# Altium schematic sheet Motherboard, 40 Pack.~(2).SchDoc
size Legal
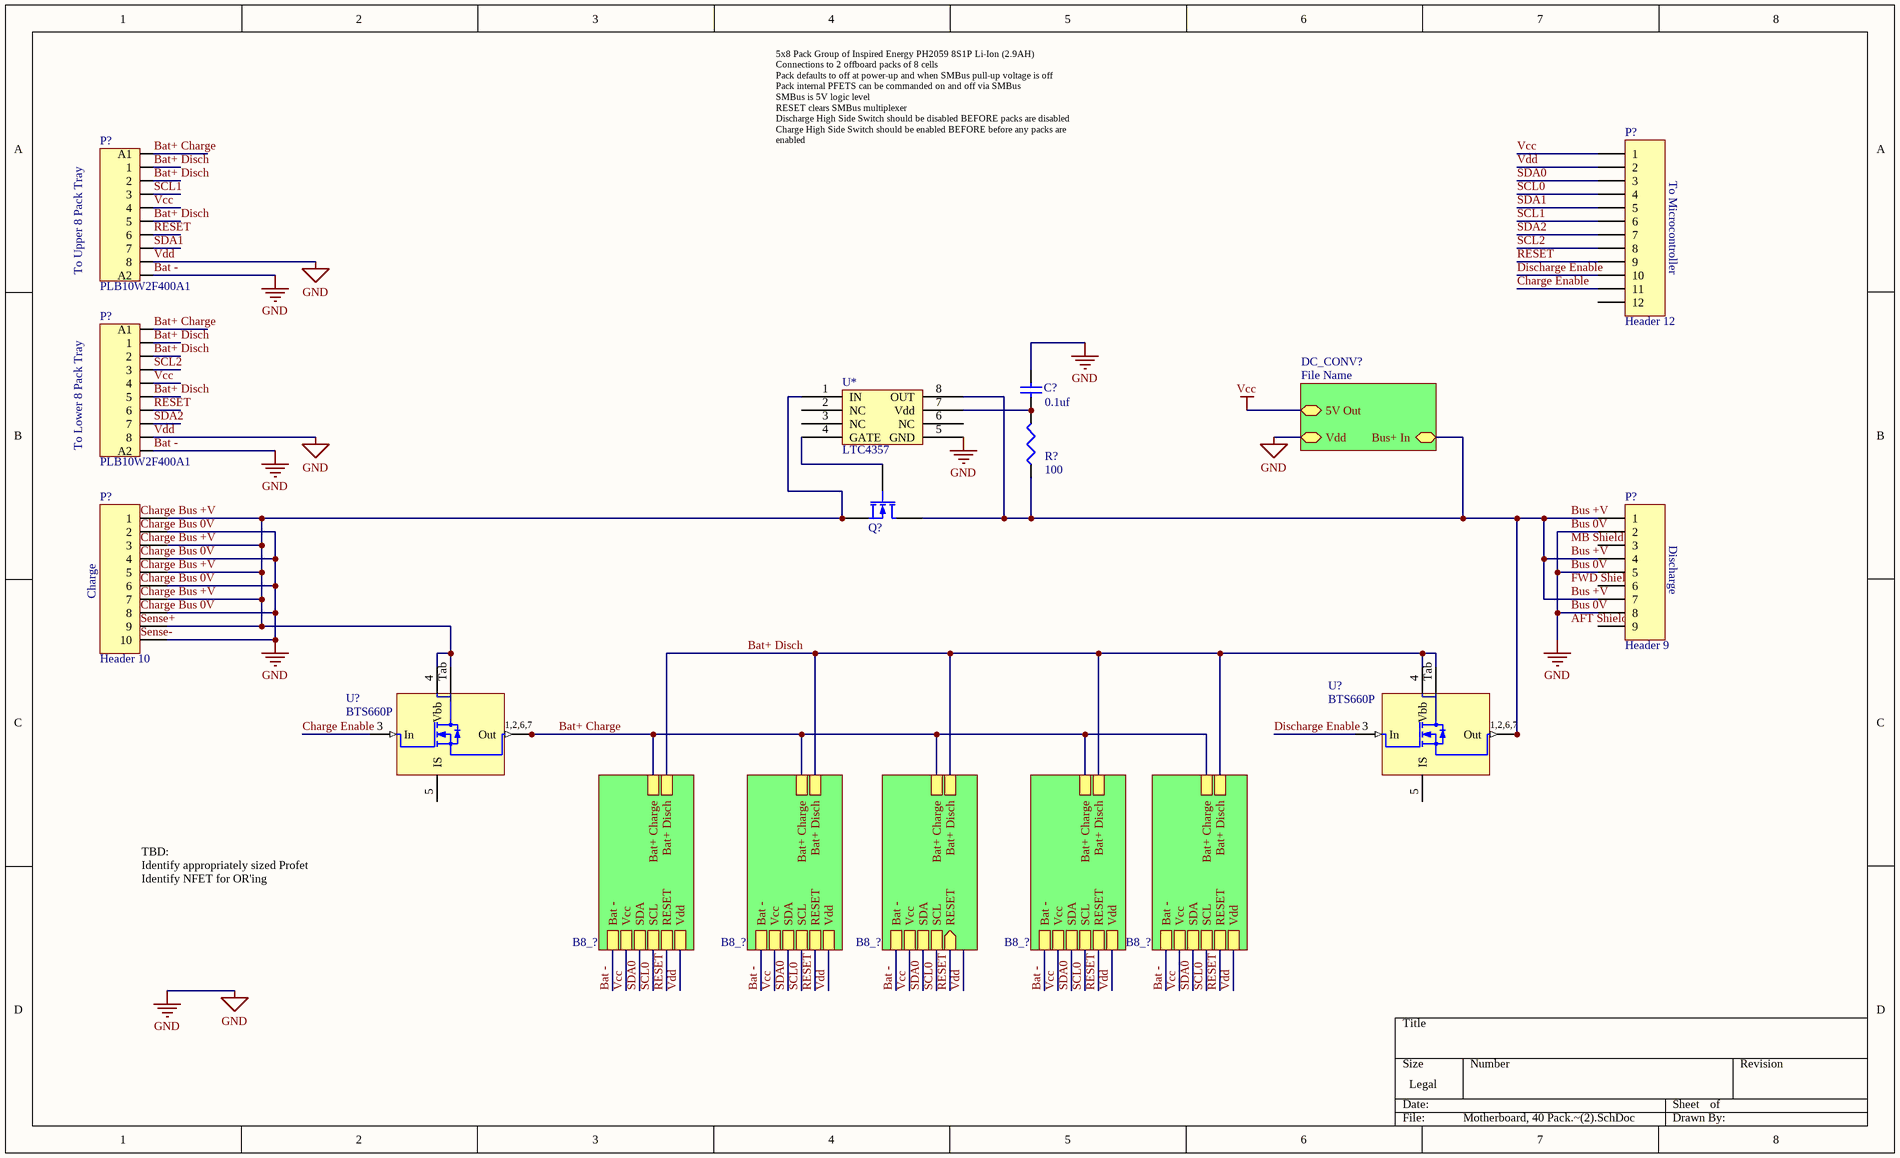
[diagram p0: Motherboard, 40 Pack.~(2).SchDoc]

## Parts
(Parts that share a designator on the sheet are numbered #1, #2 ... from top to bottom, then left to right.)
C?  value 0.1uf  [RAD-0.3]  (hidden comment: Cap)
P?#1  Header 12  [HDR1X12]
P?#2  PLB10W2F400A1
P?#3  PLB10W2F400A1
P?#4  Header 10  [HDR1X10]
P?#5  Header 9  [HDR1X9]
Q?  MOSFET-N  [BCY-W3/B.8]  (value not drawn)
R?  value 100  [RESC1608L]  (hidden comment: Res3)
U*  LTC4357
U?#1  BTS660P  [TO-220-7SMD]
U?#2  BTS660P  [TO-220-7SMD]

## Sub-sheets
B8_? = 8 Pack Controller.SchDoc: Bat+ Disch, Vcc, SDA, SCL, RESET, Bat -, Vdd, Bat+ Charge
B8_? = 8 Pack Controller.SchDoc: Bat+ Charge, Bat+ Disch, Vcc, SDA, SCL, RESET, Bat -, Vdd
B8_? = 8 Pack Controller.SchDoc: Bat+ Charge, Bat+ Disch, Vcc, SDA, SCL, RESET (in), Bat -
B8_? = 8 Pack Controller.SchDoc: Bat+ Charge, Bat+ Disch, Vcc, SDA, SCL, RESET, Bat -, Vdd
B8_? = 8 Pack Controller.SchDoc: Bat+ Charge, Bat+ Disch, Vcc, SDA, SCL, RESET, Bat -, Vdd
DC_CONV? = File Name: Bus+ In, Vdd, 5V Out

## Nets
Bat -: C?.2 P?#1.2 P?#2.8 P?#2.A2 P?#3.8 P?#3.A2 P?#4.2 P?#4.4 P?#4.6 P?#4.8 P?#4.10 P?#5.2 P?#5.5 P?#5.8 U*.5(GND) ; sheet B8_?/Bat -, sheet B8_?/Vdd, sheet B8_?/Bat -, sheet B8_?/Vdd, sheet B8_?/Bat -, sheet B8_?/Bat -, sheet B8_?/Vdd, sheet B8_?/Bat -, sheet B8_?/Vdd, sheet DC_CONV?/Vdd  [also labelled Bus 0V, GND, Vdd]
Vcc: P?#1.1 P?#2.4 P?#3.4 ; sheet B8_?/Vcc, sheet B8_?/Vcc, sheet B8_?/Vcc, sheet B8_?/Vcc, sheet B8_?/Vcc, sheet DC_CONV?/5V Out
Bat+ Charge: P?#2.A1 P?#3.A1 U?#1.1(Out) U?#1.2(Out) U?#1.6(Out) U?#1.7(Out) ; sheet B8_?/Bat+ Charge, sheet B8_?/Bat+ Charge, sheet B8_?/Bat+ Charge, sheet B8_?/Bat+ Charge, sheet B8_?/Bat+ Charge
Bat+ Disch: P?#2.1 P?#2.2 P?#2.5 P?#3.1 P?#3.2 P?#3.5 U?#2.4(Vbb) U?#2.Tab(Vbb) ; sheet B8_?/Bat+ Disch, sheet B8_?/Bat+ Disch, sheet B8_?/Bat+ Disch, sheet B8_?/Bat+ Disch, sheet B8_?/Bat+ Disch
Bus +V: P?#5.1 P?#5.4 P?#5.7 Q?.1(D) R?.1 U*.8(OUT) U?#2.1(Out) U?#2.2(Out) U?#2.6(Out) U?#2.7(Out) ; sheet DC_CONV?/Bus+ In
Charge Enable: P?#1.11 U?#1.3(In)
Discharge Enable: P?#1.10 U?#2.3(In)
RESET: P?#1.9 P?#2.6 P?#3.6 ; sheet B8_?/RESET, sheet B8_?/RESET, sheet B8_?/RESET, sheet B8_?/RESET, sheet B8_?/RESET
SCL0: P?#1.4 ; sheet B8_?/SCL, sheet B8_?/SCL, sheet B8_?/SCL, sheet B8_?/SCL, sheet B8_?/SCL
SCL1: P?#1.6 P?#2.3
SCL2: P?#1.8 P?#3.3
SDA0: P?#1.3 ; sheet B8_?/SDA, sheet B8_?/SDA, sheet B8_?/SDA, sheet B8_?/SDA, sheet B8_?/SDA
SDA1: P?#1.5 P?#2.7
SDA2: P?#1.7 P?#3.7
NetC?_1: C?.1 R?.2 U*.7(Vdd)
NetP?#4_1: P?#4.1 P?#4.3 P?#4.5 P?#4.7 P?#4.9 Q?.3(S) U*.1(IN) U?#1.4(Vbb) U?#1.Tab(Vbb)
NetQ?_2: Q?.2(G) U*.4(GATE)

Not connected (* = marked no-connect by the designer): P?#1 12; P?#5 3 6 9; U* 2(NC) 3(NC) 6(NC); U?#1 5(IS); U?#2 5(IS)

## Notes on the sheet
- 5x8 Pack Group of Inspired Energy PH2059 8S1P Li-Ion (2.9AH)
  Connections to 2 offboard packs of 8 cells
  Pack defaults to off at power-up and when SMBus pull-up voltage is off
  Pack internal PFETS can be commanded on and off via SMBus
  SMBus is 5V logic level
  RESET clears SMBus multiplexer
  Discharge High Side Switch should be disabled BEFORE packs are disabled
  Charge High Side Switch should be enabled BEFORE before any packs are enabled
- (near P?#1) To Microcontroller
- To Upper 8 Pack Tray
- To Lower 8 Pack Tray
- (near P?#5) Discharge
- (near P?#4) Charge
- TBD:
  Identify appropriately sized Profet
  Identify NFET for OR'ing
- Labels drawn without touching a wire or pin: AFT Shield, Charge Bus 0V, Charge Bus +V, FWD Shield, MB Shield, Sense+, Sense-

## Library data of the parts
C? = Cap: Capacitor
P?#1 = Header 12: Header, 12-Pin
P?#4 = Header 10: Header, 10-Pin
P?#5 = Header 9: Header, 9-Pin
Q? = MOSFET-N: N-Channel MOSFET
R? = Res3: Resistor
U?#1 U?#2 = BTS660P: High Side High Current ProFET; Manufacturer: Infineon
